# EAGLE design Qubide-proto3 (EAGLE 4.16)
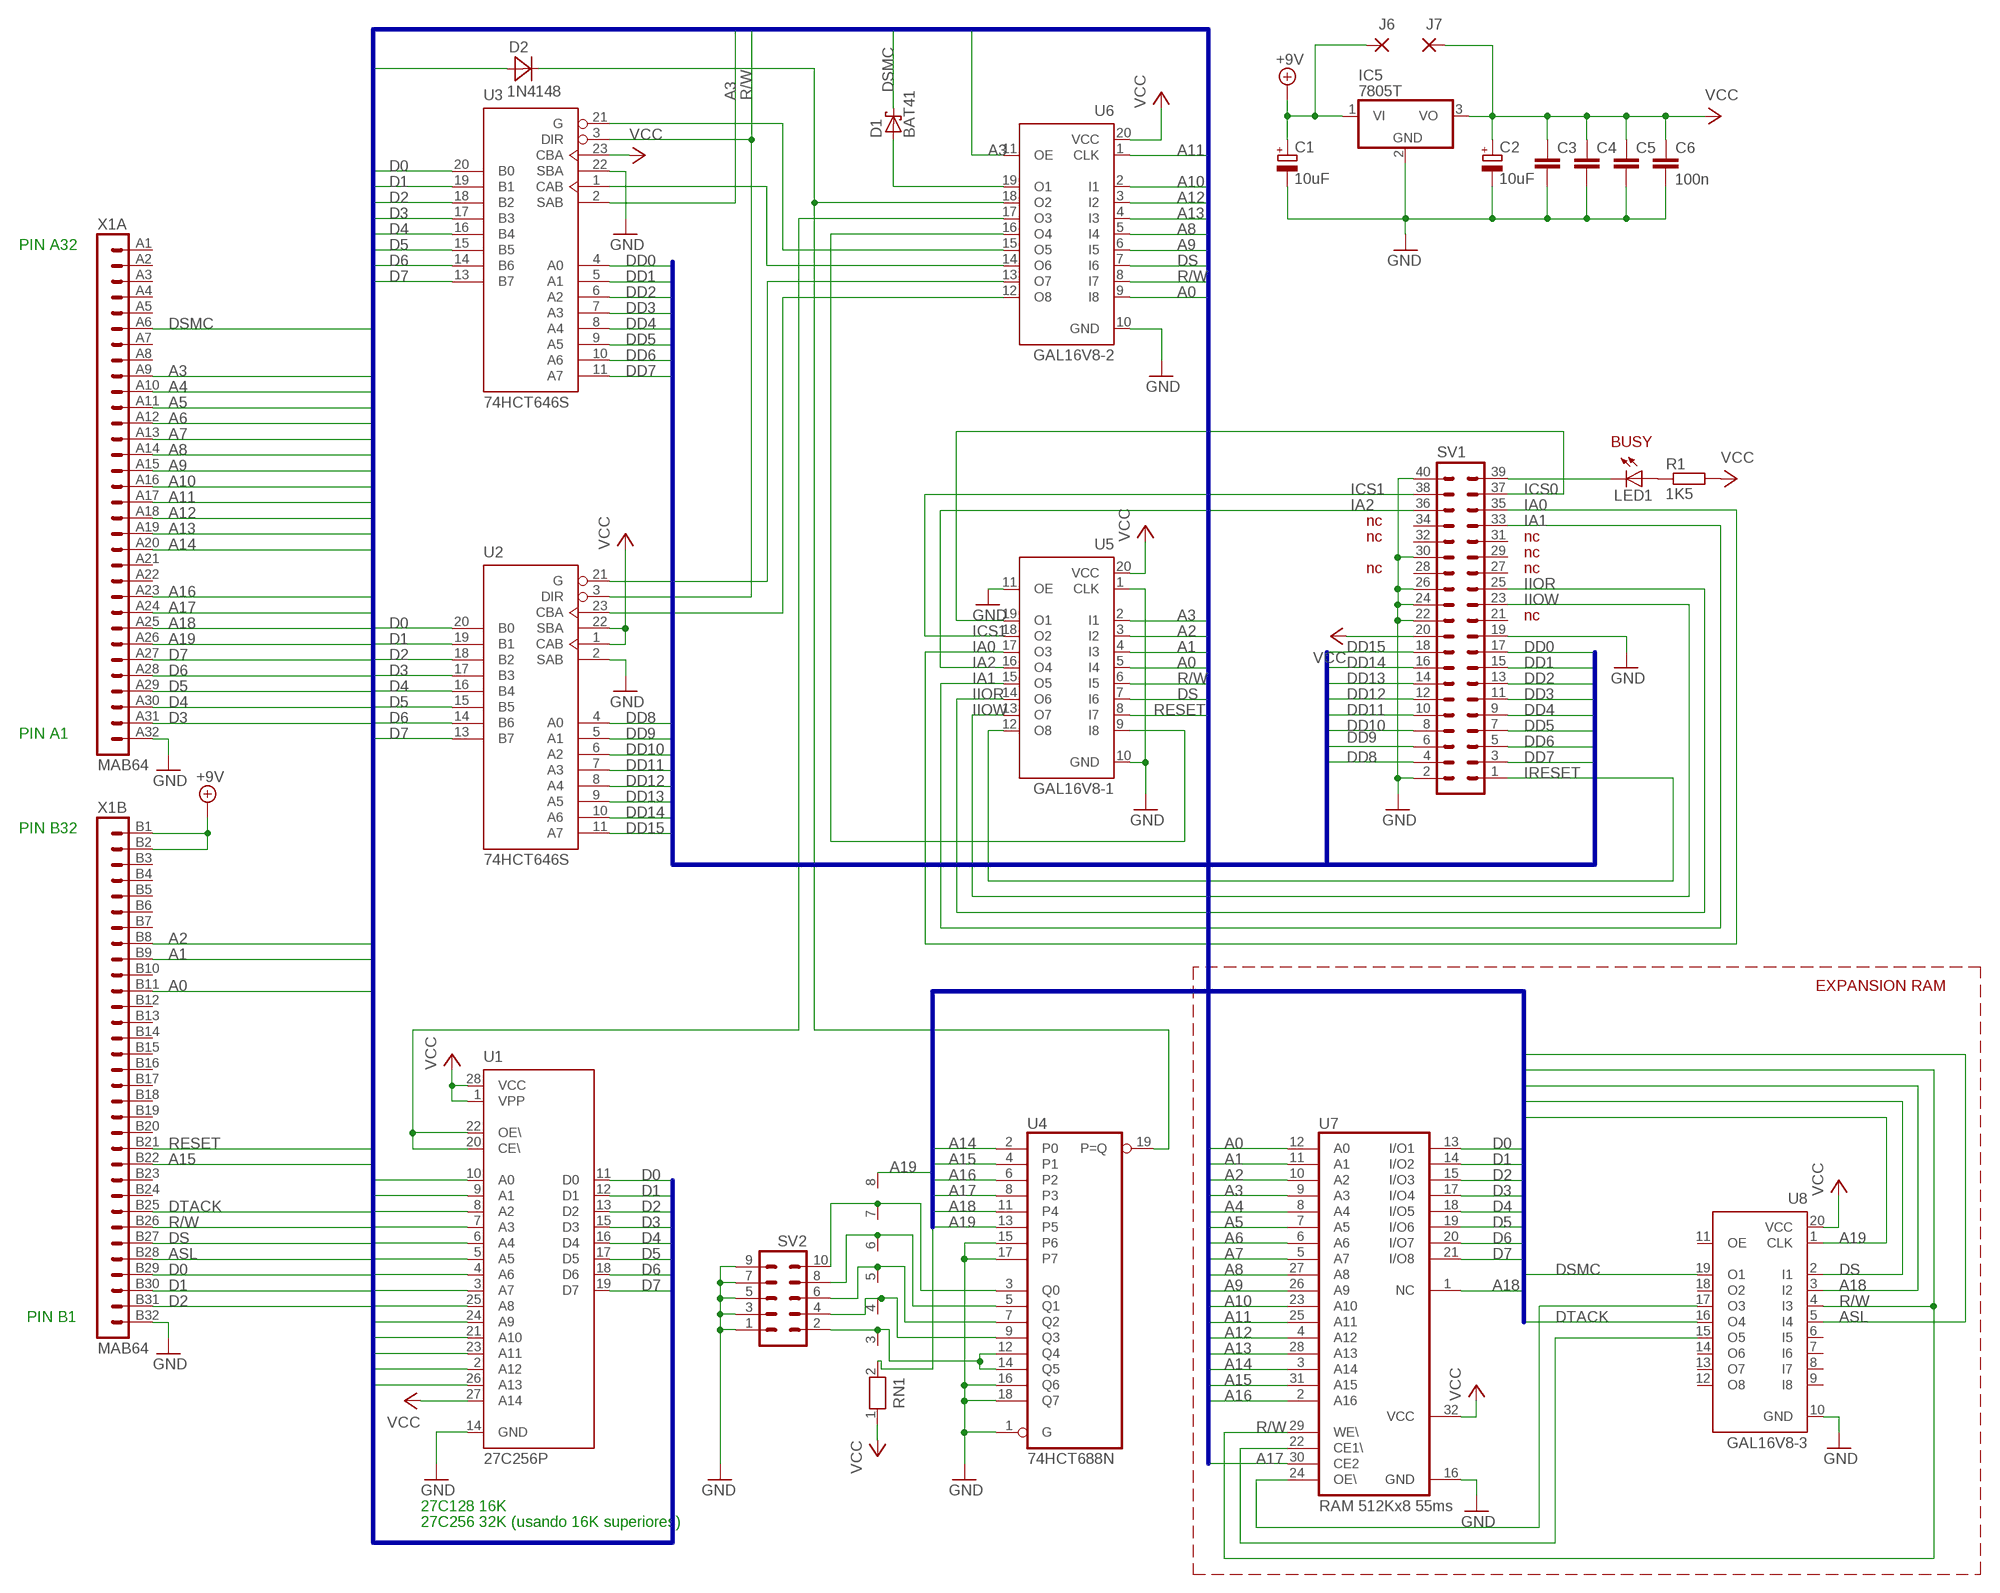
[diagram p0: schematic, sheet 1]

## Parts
C1  10uF  CPOL-EUE2.5-5  [E2,5-5]
C2  10uF  CPOL-EUE2.5-5  [E2,5-5]
C3  C-EU075-032X103  [C075-032X103]
C4  C-EU050-025X075  [C050-025X075]
C5  C-EU050-025X075  [C050-025X075]
C6  100n  C-EU050-025X075  [C050-025X075]
D1  BAT41  BAT49  [DO41-10]
D2  1N4148  DIODE-5  [D-5]
IC5  7805T  [TO220H]
J6  1,27-REDONDO1.0  [1,27/1,0-REDONDO]
J7  1,27-REDONDO1.0  [1,27/1,0-REDONDO]
LED1  LED3MM  [LED3MM]
R1  1K5  R-EU_0207/7  [0207/7]
RN1  RN07  [RN-8]
SV1  ML40L  [ML40L]
SV2  MA05-2  [MA05-2]
U1  27C256P  [DIL28-6]
U2  74HCT646S  74HC646S  [SO24W]
U3  74HCT646S  74HC646S  [SO24W]
U4  74HCT688N  [DIL20]
U5  GAL16V8-1  ATF16V8BP3  [DIL20]
U6  GAL16V8-2  ATF16V8BP3  [DIL20]
U7  RAM 512Kx8 55ms  431000  [DIL32]
U8  GAL16V8-3  ATF16V8BP3  [DIL20]
X1  MAB64  [MAB64]

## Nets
+9V: C1.+ IC5.1(VI) J6.P$1(P) X1.B1 X1.B2
A0: U1.10(A0) U5.5(I4) U6.9(I8) U7.12(A0) X1.B11
A1: U1.9(A1) U5.4(I3) U7.11(A1) X1.B9
A2: U1.8(A2) U5.3(I2) U7.10(A2) X1.B8
A3: U1.7(A3) U3.2(SAB) U5.2(I1) U6.11(OE) U7.9(A3) X1.A9
A4: U1.6(A4) U7.8(A4) X1.A10
A5: U1.5(A5) U7.7(A5) X1.A11
A6: U1.4(A6) U7.6(A6) X1.A12
A7: U1.3(A7) U7.5(A7) X1.A13
A8: U1.25(A8) U6.5(I4) U7.27(A8) X1.A14
A9: U1.24(A9) U6.6(I5) U7.26(A9) X1.A15
A10: U1.21(A10) U6.2(I1) U7.23(A10) X1.A16
A11: U1.23(A11) U6.1(CLK) U7.25(A11) X1.A17
A12: U1.2(A12) U6.3(I2) U7.4(A12) X1.A18
A13: U1.26(A13) U6.4(I3) U7.28(A13) X1.A19
A14: U4.2(P0) U7.3(A14) X1.A20
A15: U4.4(P1) U7.31(A15) X1.B22
A16: U4.6(P2) U7.2(A16) X1.A23
A17: U4.8(P3) U7.30(CE2) X1.A24
A18: RN1.2 U4.11(P4) U7.1(NC) U8.3(I2) X1.A25
A19: RN1.8 U4.13(P5) U8.1(CLK) X1.A26
ASL: U8.5(I4) X1.B28
CE-RAM: U7.22(CE1\) U8.15(O5)
D0: U1.11(D0) U2.20(B0) U3.20(B0) U7.13(I/O1) X1.B29
D1: U1.12(D1) U2.19(B1) U3.19(B1) U7.14(I/O2) X1.B30
D2: U1.13(D2) U2.18(B2) U3.18(B2) U7.15(I/O3) X1.B31
D3: U1.15(D3) U2.17(B3) U3.17(B3) U7.17(I/O4) X1.A31
D4: U1.16(D4) U2.16(B4) U3.16(B4) U7.18(I/O5) X1.A30
D5: U1.17(D5) U2.15(B5) U3.15(B5) U7.19(I/O6) X1.A29
D6: U1.18(D6) U2.14(B6) U3.14(B6) U7.20(I/O7) X1.A28
D7: U1.19(D7) U2.13(B7) U3.13(B7) U7.21(I/O8) X1.A27
DD0: SV1.17 U3.4(A0)
DD1: SV1.15 U3.5(A1)
DD2: SV1.13 U3.6(A2)
DD3: SV1.11 U3.7(A3)
DD4: SV1.9 U3.8(A4)
DD5: SV1.7 U3.9(A5)
DD6: SV1.5 U3.10(A6)
DD7: SV1.3 U3.11(A7)
DD8: SV1.4 U2.4(A0)
DD9: SV1.6 U2.5(A1)
DD10: SV1.8 U2.6(A2)
DD11: SV1.10 U2.7(A3)
DD12: SV1.12 U2.8(A4)
DD13: SV1.14 U2.9(A5)
DD14: SV1.16 U2.10(A6)
DD15: SV1.18 U2.11(A7)
DS: U5.7(I6) U6.7(I6) U8.2(I1) X1.B27
DSMC: D1.C U8.19(O1) X1.A6
DTACK: D2.A U8.16(O4) X1.B25
GND: C1.- C2.- C3.2 C4.2 C5.2 C6.2 IC5.2(GND) SV1.2 SV1.19 SV1.22 SV1.24 SV1.26 SV1.30 SV1.40 SV2.1 SV2.3 SV2.5 SV2.7 SV2.9 U1.14(GND) U2.2(SAB) U3.22(SBA) U4.1(G) U4.15(P6) U4.16(Q6) U4.17(P7) U4.18(Q7) U5.1(CLK) U5.10(GND) U5.11(OE) U6.10(GND) U7.16(GND) U8.10(GND) X1.A32 X1.B32
IA0: SV1.35 U5.17(O3)
IA1: SV1.33 U5.15(O5)
IA2: SV1.36 U5.16(O4)
ICS0: SV1.37 U5.19(O1)
ICS1: SV1.38 U5.18(O2)
IIOR: SV1.25 U5.14(O6)
IIOW: SV1.23 U5.13(O7)
IRESET: SV1.1 U5.12(O8)
N$1: D1.A U6.19(O1)
N$2: D2.C(K) U4.19(P=Q) U6.18(O2)
N$3: U1.20(CE\) U1.22(OE\) U6.17(O3)
N$4: U5.9(I8) U6.16(O4)
N$5: U3.21(G) U6.15(O5)
N$6: U3.1(CAB) U6.14(O6)
N$7: U2.21(G) U6.13(O7)
N$8: U2.23(CBA) U6.12(O8)
N$9: RN1.3 SV2.2 U4.12(Q4) U4.14(Q5)
N$10: RN1.4 SV2.4 U4.9(Q3)
N$11: RN1.5 SV2.6 U4.7(Q2)
N$12: RN1.6 SV2.8 U4.5(Q1)
N$13: RN1.7 SV2.10 U4.3(Q0)
N$14: LED1.A R1.1
N$15: LED1.K(C) SV1.39
OE-RAM: U7.24(OE\) U8.17(O3)
R/W: U2.3(DIR) U3.3(DIR) U5.6(I5) U6.8(I7) U7.29(WE\) U8.4(I3) X1.B26
RESET: U5.8(I7) X1.B21
VCC: C2.+ C3.1 C4.1 C5.1 C6.1 IC5.3(VO) J7.P$1(P) R1.2 RN1.1 SV1.20 U1.1(VPP) U1.27(A14) U1.28(VCC) U2.1(CAB) U2.22(SBA) U3.23(CBA) U5.20(VCC) U6.20(VCC) U7.32(VCC) U8.20(VCC)
Unconnected: SV1.21 SV1.27 SV1.28 SV1.29 SV1.31 SV1.32 SV1.34 U8.6(I5) U8.7(I6) U8.8(I7) U8.9(I8) U8.11(OE) U8.12(O8) U8.13(O7) U8.14(O6) U8.18(O2) X1.A1 X1.A2 X1.A3 X1.A4 X1.A5 X1.A7 X1.A8 X1.A21 X1.A22 X1.B3 X1.B4 X1.B5 X1.B6 X1.B7 X1.B10 X1.B12 X1.B13 X1.B14 X1.B15 X1.B16 X1.B17 X1.B18 X1.B19 X1.B20 X1.B23 X1.B24

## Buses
A[0..19],D[0..7],DSMC,DTACK,R/W,DS,RESET,ASL
DD[0..15]

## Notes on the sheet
- PIN A32
- BUSY
- nc
- nc | nc
- nc
- nc | nc
- nc
- PIN A1
- PIN B32
- EXPANSION RAM
- PIN B1
- 27C128 16K
- 27C256 32K (usando 16K superiores)

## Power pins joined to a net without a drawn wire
GND: U2.12(GND) U3.12(GND) U4.10(GND)
VCC: U2.24(VCC) U3.24(VCC) U4.20(VCC)

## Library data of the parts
C1 C2 = rcl:CPOL-EU: POLARIZED CAPACITOR, European symbol
C3-C6 = rcl:C-EU: CAPACITOR, European symbol
D1 = diode:BAT49: DIODE
D2 = discrete2:DIODE-5
IC5 = linear:78*: Positive VOLTAGE REGULATOR Source: http://cache.national.com/ds/LM/LM78L05.pdf http://www.fairchildsemi.com/ds/LM/LM7805.pdf
J6 J7 = wirepad2:1,27-REDONDO
LED1 = led:LED: LED
R1 = rcl:R-EU_: RESISTOR, European symbol
RN1 = discrete2:RN07
SV1 = con-harting-ml:ML40: HARTING
SV2 = con-lstb:MA05-2: PIN HEADER
U1 = microchip:27*256: CMOS EPROM 256 K (32 K x 8), low voltage
U2 U3 = 74xx-eu2:74*646
U4 = 74xx-eu:74*688: 8-bit MAGNITUDE/IDENTITY COMPARATOR, totem pole
U5 U6 U8 = atmel:ATF16V8B: High perfomance CMOS (electrically erasable) programmable logic device (PLD) ABLE-Atmel-ABEL - P18V8R, P16V8C, P16V8AS, P17V8 COPL Atmel-WinCUPL - G16V8MS, G16V8MA, G16V8AS, G16V8 LOG/IC - GAL16V8_R, GAL16V8_G7, GAL16V8_C), GAL16V8 Tango-PLD - G16V8R, G16V8C, G16V8AS, G16V8 Source: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
U7 = memory-nec:431000: MEMORY
X1 = con-vg:MAB64: CONNECTOR male, 94 pins, type B, rows AB, grid 2.54 mm

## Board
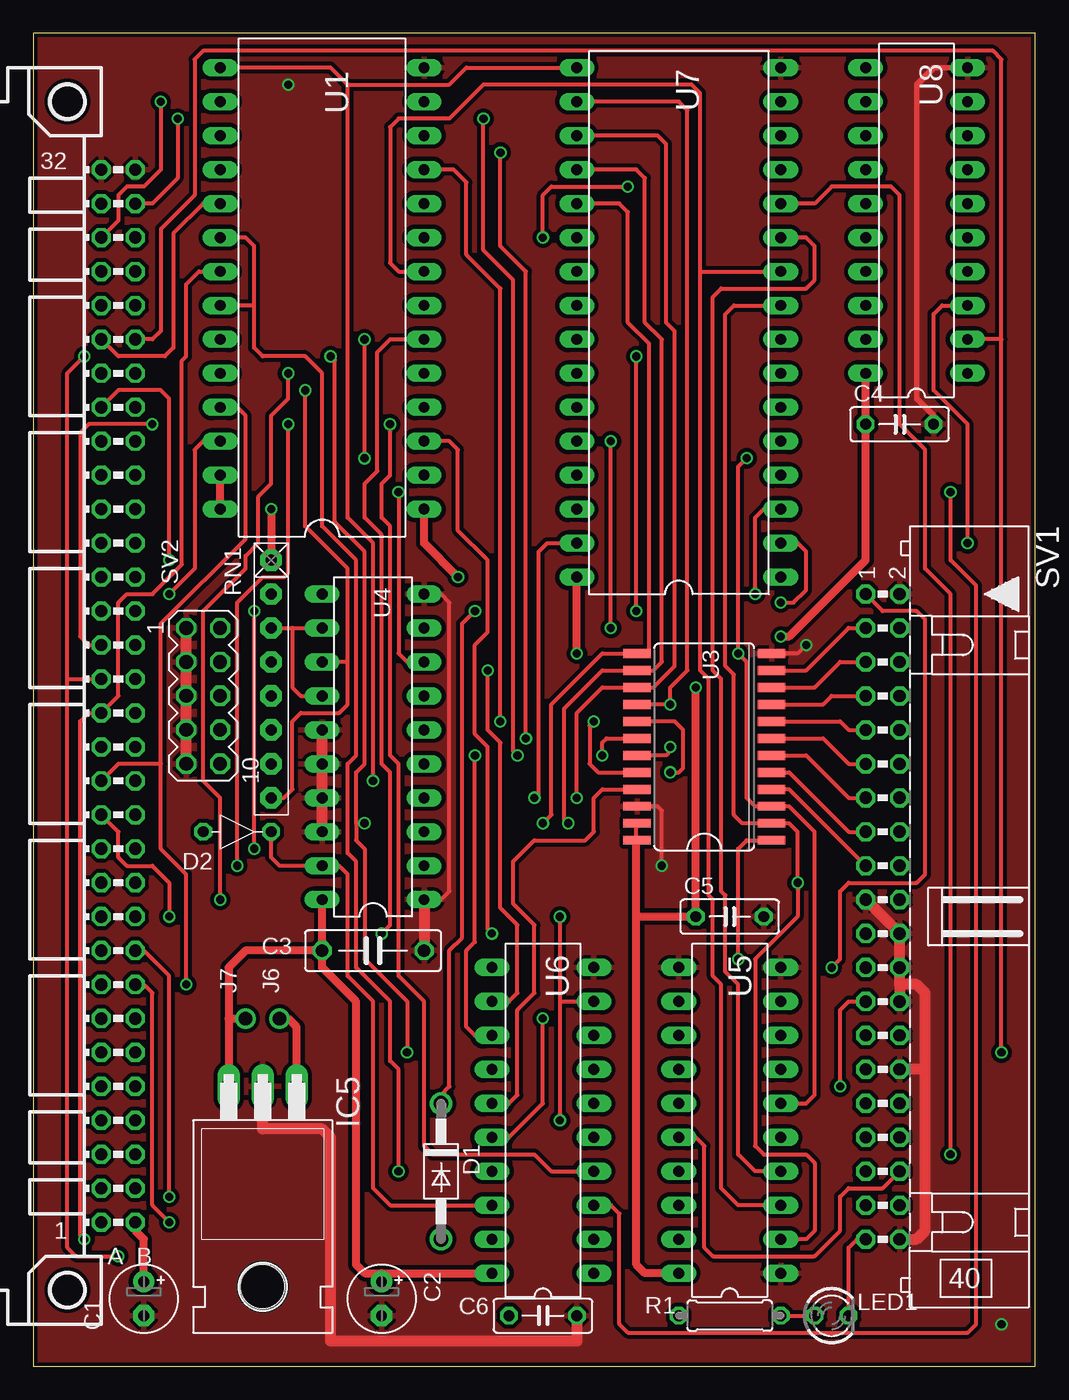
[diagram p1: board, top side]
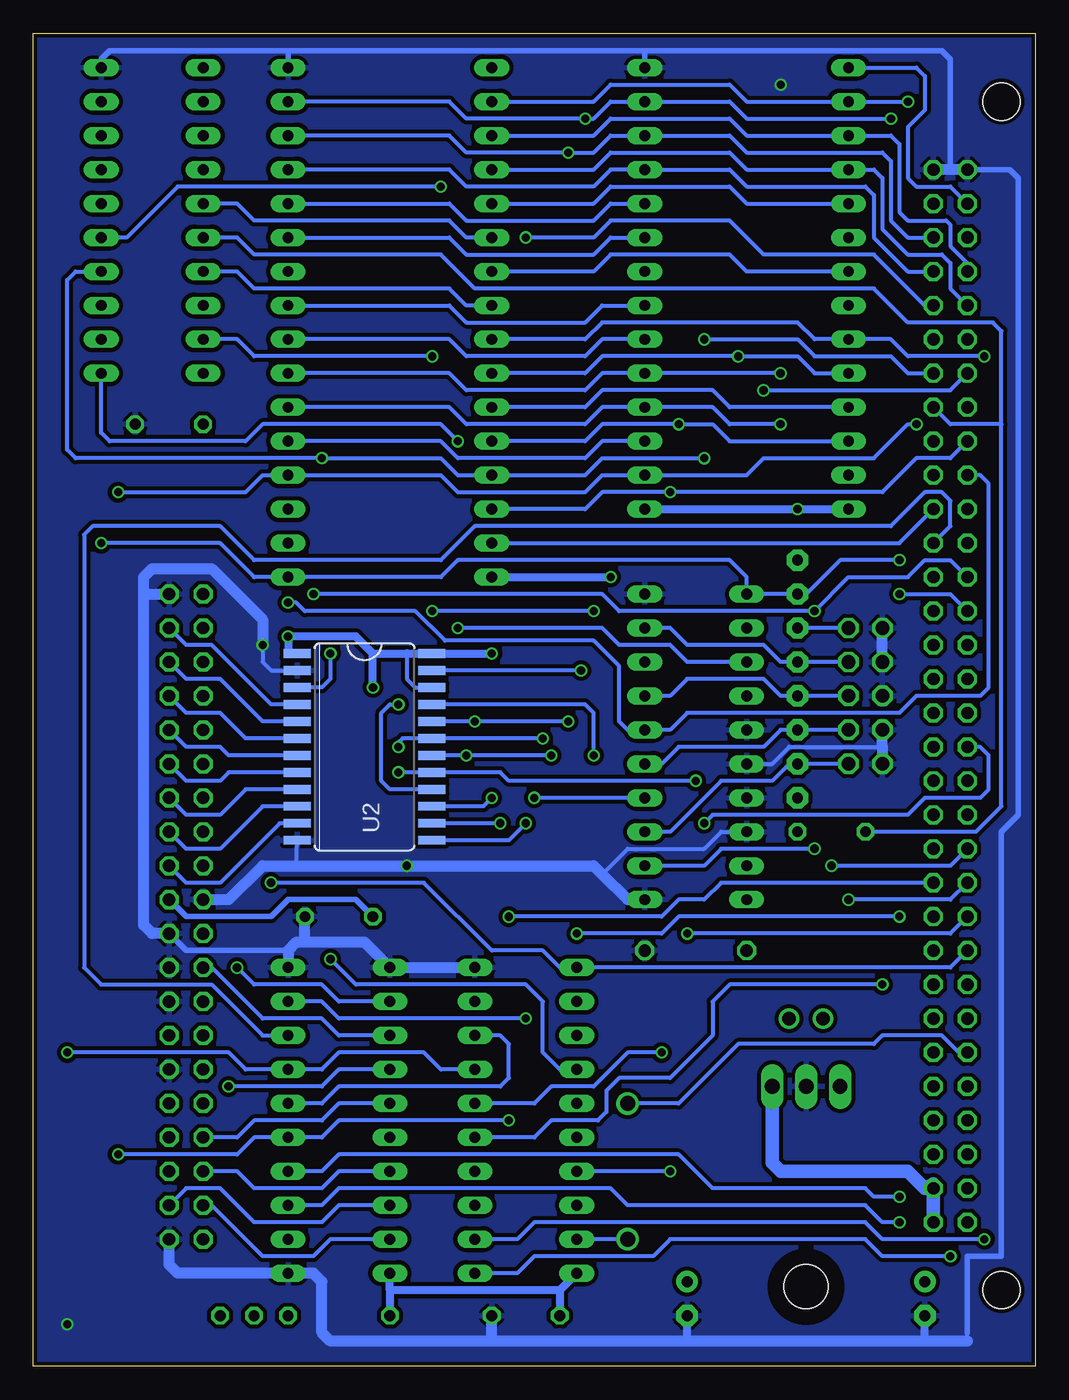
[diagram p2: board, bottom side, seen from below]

Size 74.91 x 99.68 mm. Coordinates in mm from the lower left corner, seen from the top.
Outline: 0,0 74.91,0 74.91,99.68 0,99.68 0,0
Copper layers (1*16): Top 0.035mm / dielectric 1.5mm / Bottom 0.035mm
Design rules "ITEADstudio_DRC": minimum track width 6mil, minimum drill 12mil, track to track 6mil, track to pad 6mil, pad to pad 6mil, via to via 6mil, smd to smd 0mil, copper to edge 10mil, drill to drill 10mil, minimum pad ring 10mil, minimum via ring 6mil, stop-mask expansion 2mil, vias tented up to drill 100mil, thermal gap 10mil

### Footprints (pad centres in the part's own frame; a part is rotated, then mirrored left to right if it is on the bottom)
E2,5-5 = drill 0.813 pad 1.6 round: + -1.27,0 | drill 0.813 pad 1.6 octagon: - 1.27,0
C075-032X103 = drill 0.914 octagon: 1 -3.81,0; 2 3.81,0
C050-025X075 = drill 0.813 octagon: 1 -2.54,0; 2 2.54,0
DO41-10 = drill 1.118 round: A 5.08,0; C -5.08,0
D-5 = drill 0.813 octagon: A -2.54,0; C 2.54,0
TO220H = drill 1.118 long: 1 -2.54,-10.16; 2 0,-10.16; 3 2.54,-10.16 | hole 3.302: 0,4.826
1,27/1,0-REDONDO = drill 1.016 pad 1.422 round: P$1 0,0
LED3MM = drill 0.813 octagon: A -1.27,0; K 1.27,0
0207/7 = drill 0.813 octagon: 1 -3.81,0; 2 3.81,0
RN-8 = drill 0.813 pad 1.6 octagon: 1 -8.89,0; 2 -6.35,0; 3 -3.81,0; 4 -1.27,0; 5 1.27,0; 6 3.81,0; 7 6.35,0; 8 8.89,0
ML40L = drill 0.914 octagon: 1 -24.13,-1.27; 2 -24.13,1.27; 3 -21.59,-1.27; 4 -21.59,1.27; 5 -19.05,-1.27; 6 -19.05,1.27; 7 -16.51,-1.27; 8 -16.51,1.27; 9 -13.97,-1.27; 10 -13.97,1.27; 11 -11.43,-1.27; 12 -11.43,1.27; 13 -8.89,-1.27; 14 -8.89,1.27; 15 -6.35,-1.27; 16 -6.35,1.27; 17 -3.81,-1.27; 18 -3.81,1.27; 19 -1.27,-1.27; 20 -1.27,1.27; 21 1.27,-1.27; 22 1.27,1.27; 23 3.81,-1.27; 24 3.81,1.27; 25 6.35,-1.27; 26 6.35,1.27; 27 8.89,-1.27; 28 8.89,1.27; 29 11.43,-1.27; 30 11.43,1.27; 31 13.97,-1.27; 32 13.97,1.27; 33 16.51,-1.27; 34 16.51,1.27; 35 19.05,-1.27; 36 19.05,1.27; 37 21.59,-1.27; 38 21.59,1.27; 39 24.13,-1.27; 40 24.13,1.27
MA05-2 = drill 1.016 octagon: 1 -5.08,-1.27; 2 -5.08,1.27; 3 -2.54,-1.27; 4 -2.54,1.27; 5 0,-1.27; 6 0,1.27; 7 2.54,-1.27; 8 2.54,1.27; 9 5.08,-1.27; 10 5.08,1.27
DIL28-6 = drill 0.813 long: 1 -16.51,-7.62; 2 -13.97,-7.62; 3 -11.43,-7.62; 4 -8.89,-7.62; 5 -6.35,-7.62; 6 -3.81,-7.62; 7 -1.27,-7.62; 8 1.27,-7.62; 9 3.81,-7.62; 10 6.35,-7.62; 11 8.89,-7.62; 12 11.43,-7.62; 13 13.97,-7.62; 14 16.51,-7.62; 15 16.51,7.62; 16 13.97,7.62; 17 11.43,7.62; 18 8.89,7.62; 19 6.35,7.62; 20 3.81,7.62; 21 1.27,7.62; 22 -1.27,7.62; 23 -3.81,7.62; 24 -6.35,7.62; 25 -8.89,7.62; 26 -11.43,7.62; 27 -13.97,7.62; 28 -16.51,7.62
SO24W = smd 0.66 x 2.032: 1 -6.985,-5.029; 2 -5.715,-5.029; 3 -4.445,-5.029; 4 -3.175,-5.029; 5 -1.905,-5.029; 6 -0.635,-5.029; 7 0.635,-5.029; 8 1.905,-5.029; 9 3.175,-5.029; 10 4.445,-5.029; 11 5.715,-5.029; 12 6.985,-5.029; 13 6.985,5.029; 14 5.715,5.029; 15 4.445,5.029; 16 3.175,5.029; 17 1.905,5.029; 18 0.635,5.029; 19 -0.635,5.029; 20 -1.905,5.029; 21 -3.175,5.029; 22 -4.445,5.029; 23 -5.715,5.029; 24 -6.985,5.029
DIL20 = drill 0.813 long: 1 -11.43,-3.81; 2 -8.89,-3.81; 3 -6.35,-3.81; 4 -3.81,-3.81; 5 -1.27,-3.81; 6 1.27,-3.81; 7 3.81,-3.81; 8 6.35,-3.81; 9 8.89,-3.81; 10 11.43,-3.81; 11 11.43,3.81; 12 8.89,3.81; 13 6.35,3.81; 14 3.81,3.81; 15 1.27,3.81; 16 -1.27,3.81; 17 -3.81,3.81; 18 -6.35,3.81; 19 -8.89,3.81; 20 -11.43,3.81
DIL32 = drill 0.813 long: 1 -19.05,-7.62; 2 -16.51,-7.62; 3 -13.97,-7.62; 4 -11.43,-7.62; 5 -8.89,-7.62; 6 -6.35,-7.62; 7 -3.81,-7.62; 8 -1.27,-7.62; 9 1.27,-7.62; 10 3.81,-7.62; 11 6.35,-7.62; 12 8.89,-7.62; 13 11.43,-7.62; 14 13.97,-7.62; 15 16.51,-7.62; 16 19.05,-7.62; 17 19.05,7.62; 18 16.51,7.62; 19 13.97,7.62; 20 11.43,7.62; 21 8.89,7.62; 22 6.35,7.62; 23 3.81,7.62; 24 1.27,7.62; 25 -1.27,7.62; 26 -3.81,7.62; 27 -6.35,7.62; 28 -8.89,7.62; 29 -11.43,7.62; 30 -13.97,7.62; 31 -16.51,7.62; 32 -19.05,7.62
MAB64 = drill 0.914 octagon: A1 -2.54,39.37; A2 -2.54,36.83; A3 -2.54,34.29; A4 -2.54,31.75; A5 -2.54,29.21; A6 -2.54,26.67; A7 -2.54,24.13; A8 -2.54,21.59; A9 -2.54,19.05; A10 -2.54,16.51; A11 -2.54,13.97; A12 -2.54,11.43; A13 -2.54,8.89; A14 -2.54,6.35; A15 -2.54,3.81; A16 -2.54,1.27; A17 -2.54,-1.27; A18 -2.54,-3.81; A19 -2.54,-6.35; A20 -2.54,-8.89; A21 -2.54,-11.43; A22 -2.54,-13.97; A23 -2.54,-16.51; A24 -2.54,-19.05; A25 -2.54,-21.59; A26 -2.54,-24.13; A27 -2.54,-26.67; A28 -2.54,-29.21; A29 -2.54,-31.75; A30 -2.54,-34.29; A31 -2.54,-36.83; A32 -2.54,-39.37; B1 -5.08,39.37; B2 -5.08,36.83; B3 -5.08,34.29; B4 -5.08,31.75; B5 -5.08,29.21; B6 -5.08,26.67; B7 -5.08,24.13; B8 -5.08,21.59; B9 -5.08,19.05; B10 -5.08,16.51; B11 -5.08,13.97; B12 -5.08,11.43; B13 -5.08,8.89; B14 -5.08,6.35; B15 -5.08,3.81; B16 -5.08,1.27; B17 -5.08,-1.27; B18 -5.08,-3.81; B19 -5.08,-6.35; B20 -5.08,-8.89; B21 -5.08,-11.43; B22 -5.08,-13.97; B23 -5.08,-16.51; B24 -5.08,-19.05; B25 -5.08,-21.59; B26 -5.08,-24.13; B27 -5.08,-26.67; B28 -5.08,-29.21; B29 -5.08,-31.75; B30 -5.08,-34.29; B31 -5.08,-36.83; B32 -5.08,-39.37 | hole 2.794: 0,44.45; 0,-44.45

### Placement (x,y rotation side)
C1  8.25,5.04 270 top
C2  26.03,5.04 270 top
C3  25.39,31.08 0 top
C4  64.77,70.45 0 top
C5  52.06,33.62 0 top
C6  38.09,3.77 0 top
D1  30.48,14.57 270 top
D2  15.23,39.97 0 top
IC5  17.14,10.76 180 top
J6  18.41,26 270 top
J7  15.87,26 90 top
LED1  59.68,3.77 0 top
R1  52.06,3.77 180 top
RN1  17.78,51.4 270 top
SV1  63.49,33.62 270 top
SV2  12.69,50.13 270 top
U1  21.59,80.61 90 top
U2  50.16,46.32 270 bottom
U3  50.16,46.32 90 top
U4  25.39,46.32 90 top
U5  52.06,18.38 90 top
U6  38.09,18.38 90 top
U7  48.25,78.07 90 top
U8  66.04,85.69 90 top
X1  2.54,50.13 180 top

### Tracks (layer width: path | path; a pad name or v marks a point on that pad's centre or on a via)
+9V
  Top 0.61: J6.P$1 19.05,26 19.68,25.36 IC5.1 | C1.+ 8.25,9.49 7.62,10.12 X1.B1
  Bottom 0.813: X1.B2 7.62,13.61
  Bottom 1.016: X1.B1 X1.B2 | 7.62,13.61 8.25,13.3 9.52,14.57 19.05,14.57 19.68,15.2 IC5.1
A0  (via drill 0.61)
  Top 0.305: 39.36,27.27 v39.36,18.38 | v39.36,33.62 39.36,27.27 | 39.36,27.27 U6.9 | v68.58,15.84 68.58,57.75 66.67,59.65 66.67,68.54 64.77,70.45 64.77,87.59 64.13,88.23 59.68,88.23 58.41,86.96 U7.12
  Bottom 0.305: U1.10 31.75,86.96 33.02,85.69 42.54,85.69 43.81,86.96 U7.12 | v39.36,18.38 52.06,18.38 53.34,17.11 U5.5 58.41,17.11 59.68,15.84 v68.58,15.84 | v39.36,33.62 27.94,33.62 26.67,34.89 24.76,34.89 23.49,36.16 X1.B11
A1  (via drill 0.61)
  Top 0.305: v10.15,12.66 10.15,29.17 8.25,31.08 X1.B9 | U5.4 53.97,14.57 52.7,15.84 52.7,28.54 51.75,29.49 51.75,35.2 51.43,35.52 51.43,51.4 50.79,52.03 50.79,79.97 51.43,80.61 57.78,80.61 58.41,81.24 58.41,83.78 57.78,84.42 U7.11
  Bottom 0.305: U1.9 31.75,84.42 33.02,83.15 42.54,83.15 43.81,84.42 U7.11 | v10.15,12.66 12.06,12.66 12.69,13.3 24.12,13.3 26.67,15.84 52.06,15.84 53.34,14.57 U5.4
A2  (via drill 0.61)
  Top 0.305: 49.84,81.88 49.84,95.21 49.21,95.85 33.65,95.85 31.11,93.31 27.3,93.31 26.67,92.67 26.67,82.51 27.3,81.88 U1.8 | 49.84,81.88 U7.10 | v10.15,10.76 8.88,12.03 8.88,27.9 8.25,28.54 X1.B8 | 49.84,81.88 49.84,52.03 50.48,51.4 50.48,35.2 50.79,34.89 50.79,29.17 51.43,28.54 51.43,13.3 52.7,12.03 U5.3
  Bottom 0.305: v10.15,10.76 11.42,10.76 12.69,12.03 30.48,12.03 31.75,13.3 52.06,13.3 53.34,12.03 U5.3
A3  (via drill 0.61)
  Top 0.305: U3.2 56.51,40.6 57.14,39.97 v57.14,36.16 57.14,33.62 53.97,30.44 53.97,16.47 54.6,15.84 57.78,15.84 58.41,15.2 58.41,10.12 57.78,9.49 U5.2 | U7.9 52.38,79.34 51.75,78.7 51.75,52.35 52.38,51.71 52.38,41.24 53.02,40.6 U3.2 | U3.2 55.24,40.6
  Bottom 0.305: X1.A9 6.34,29.81 U6.11 35.55,29.81 36.82,31.08 40.63,31.08 45.71,36.16 v57.14,36.16 | U1.7 32.38,79.34 33.65,78.07 42.54,78.07 43.81,79.34 U7.9
A4  (via drill 0.6)
  Top 0.305: U1.6 26.67,76.8 25.71,75.84 25.71,66.95 24.76,66 24.76,63.46 26.03,62.19 26.03,45.05 26.67,44.41 26.67,32.98 v26.03,32.35
  Bottom 0.305: U1.6 32.38,76.8 33.65,75.53 42.54,75.53 43.81,76.8 U7.8 | X1.A10 6.34,32.35 v26.03,32.35
A5  (via drill 0.61)
  Top 0.305: v13.96,34.89 13.96,42.51 12.69,43.78 12.69,56.48 15.87,59.65 15.87,60.6 16.82,61.56 16.82,65.05 17.78,66 17.78,71.08 19.05,72.35 v19.05,74.26
  Bottom 0.305: U7.7 43.81,74.26 42.54,72.99 33.65,72.99 32.38,74.26 U1.5 v19.05,74.26 | X1.A11 6.34,34.89 v13.96,34.89
A6  (via drill 0.61)
  Top 0.305: v15.23,37.43 15.23,57.11 17.14,59.02 18.73,59.02 19.05,59.34 v19.05,70.45
  Bottom 0.305: U7.6 43.81,71.72 42.54,70.45 33.65,70.45 32.38,71.72 U1.4 24.12,71.72 22.86,70.45 v19.05,70.45 | v15.23,37.43 6.34,37.43 X1.A12
A7  (via drill 0.6)
  Top 0.305: U1.3 31.11,69.18 31.75,68.54 31.75,62.51 33.97,60.29 33.97,54.89 33.02,53.94 33.02,47.27 33.97,46.32 33.97,32.67 v34.28,32.35 | X1.A13 6.34,39.97 6.34,38.06 6.98,37.43 8.88,37.43 10.15,36.16 v10.15,33.62
  Bottom 0.305: U1.3 32.38,69.18 33.65,67.91 43.17,67.91 44.45,69.18 U7.5 | v10.15,33.62 26.67,33.62 27.94,32.35 v34.28,32.35
A8  (via drill 0.6)
  Top 0.305: v11.42,28.54 11.42,36.79 9.52,38.7 9.52,45.05 | 9.52,45.05 6.34,45.05 X1.A14 | U1.25 15.23,71.72 15.87,71.08 15.87,61.88 9.52,55.52 9.52,45.05
  Bottom 0.305: U1.25 22.86,71.72 24.12,72.99 32.38,72.99 33.65,71.72 U7.27 | U6.5 37.46,17.11 36.19,18.38 32.7,18.38 32.06,19.01 32.06,20.6 31.11,21.55 27.3,21.55 24.12,24.73 24.12,27.27 22.86,28.54 v11.42,28.54
A9  (via drill 0.61)
  Top 0.305: v27.94,23.46 27.94,27.27 24.76,30.44 24.76,38.7 24.12,39.33 24.12,40.6 | v22.22,75.53 22.54,75.21 22.54,63.14 24.76,60.92 24.76,45.05 24.12,44.41 24.12,40.6 | v24.76,40.6 24.12,40.6
  Bottom 0.305: U1.24 16.51,74.26 17.78,75.53 v22.22,75.53 32.38,75.53 33.65,74.26 U7.26 | U6.6 37.46,19.65 36.19,20.92 33.02,20.92 30.48,23.46 v27.94,23.46 | v24.76,40.6 24.12,41.24 9.52,41.24 8.25,42.51 4.12,42.51 3.49,43.14 3.49,45.68 4.12,46.32 X1.A15
A10  (via drill 0.61)
  Top 0.305: v3.81,9.49 3.49,9.8 3.49,48.22 4.12,48.86 X1.A16 6.34,50.13 6.34,57.11 6.98,57.75 8.88,57.75 11.11,59.97 11.11,75.21 11.42,75.53 11.42,80.92 12.38,81.88 U1.21
  Bottom 0.305: U1.21 21.59,81.88 22.86,83.15 31.75,83.15 33.02,81.88 U7.23 | v3.81,9.49 11.42,9.49 12.69,10.76 37.46,10.76 38.73,9.49 U6.2
A11  (via drill 0.61)
  Top 0.305: v6.34,8.22 3.17,8.22 2.54,8.85 2.54,51.4 | 2.54,51.4 X1.A17 | 2.54,51.4 2.54,74.26 v3.81,75.53
  Bottom 0.305: U7.25 33.65,76.8 32.38,78.07 17.78,78.07 16.51,76.8 U1.23 10.79,76.8 9.52,75.53 v3.81,75.53 | v6.34,8.22 11.42,8.22 12.69,9.49 27.3,9.49 28.57,8.22 37.46,8.22 38.73,6.95 U6.1
A12  (via drill 0.61)
  Top 0.305: v68.58,65.37 68.58,60.29 70.48,58.38 70.48,3.14 69.84,2.5 44.45,2.5 43.81,3.14 43.81,11.39 43.17,12.03 U6.3 | v8.88,70.45 4.12,70.45 3.49,69.81 3.49,54.57 4.12,53.94 X1.A18
  Bottom 0.305: v68.58,65.37 59.05,65.37 57.78,66.64 U7.4 44.45,66.64 43.17,65.37 33.65,65.37 32.38,66.64 U1.2 21.59,66.64 20.32,67.91 12.06,67.91 9.52,70.45 v8.88,70.45
A13  (via drill 0.61)
  Top 0.305: v26.67,70.45 26.67,66.64 26.03,66 26.03,63.46 26.67,62.83 26.67,45.68 27.3,45.05 27.3,29.17 29.21,27.27 29.21,16.47 29.84,15.84 37.46,15.84 38.73,14.57 U6.4 | v10.15,57.75 12.06,59.65 12.06,68.54 12.69,69.18 U1.26
  Bottom 0.305: U1.26 22.86,69.18 24.12,70.45 v26.67,70.45 32.38,70.45 33.65,69.18 U7.28 | v10.15,57.75 6.34,57.75 X1.A19
A14  (via drill 0.61)
  Top 0.305: v53.97,57.75 53.97,63.46 54.6,64.1 U7.3 | v16.51,38.7 v16.51,56.48
  Bottom 0.305: v16.51,38.7 23.49,38.7 24.76,37.43 U4.2 | v53.97,57.75 32.38,57.75 31.11,56.48 v16.51,56.48 13.96,59.02 9.52,59.02 8.25,60.29 6.34,60.29 X1.A20
A15  (via drill 0.61)
  Top 0.305: v37.46,42.51 37.78,42.82 37.78,60.92 38.41,61.56 U7.31
  Bottom 0.305: U4.4 v37.46,42.51 | X1.B22 10.15,61.56 U7.31
A16  (via drill 0.61)
  Top 0.305: v55.88,57.11 56.83,57.11 57.78,58.06 57.78,60.92 57.14,61.56 U7.2
  Bottom 0.305: v55.88,57.11 55.24,57.11 54.6,56.48 46.35,56.48 44.13,54.25 33.02,54.25 31.11,52.35 31.11,48.22 30.48,47.59 U4.6 27.3,47.59 26.03,48.86 10.15,48.86 8.88,50.13 4.12,50.13 3.49,50.76 3.49,66 4.12,66.64 X1.A23
A17  (via drill 0.61)
  Top 0.305: U4.8 27.94,52.67 27.3,53.3 v27.3,65.37
  Bottom 0.305: U7.30 33.65,64.1 32.38,65.37 v27.3,65.37 11.42,65.37 8.88,67.91 6.34,67.91 X1.A24
A18  (via drill 0.61)
  Top 0.305: v69.84,61.56 69.84,70.45 67.31,72.99 67.31,78.7 67.94,79.34 U8.3 | X1.A25 6.34,72.99 9.52,72.99 10.15,72.35 v10.15,60.29
  Bottom 0.305: v69.84,61.56 60.95,61.56 58.41,59.02 U7.1 44.45,59.02 43.17,60.29 22.86,60.29 21.59,59.02 U4.11 RN1.2 17.14,57.75 14.6,60.29 v10.15,60.29
A19  (via drill 0.61)
  Top 0.305: 23.49,52.67 23.49,49.49 22.86,48.86 20,48.86 19.36,48.22 19.36,43.14 18.73,42.51 RN1.8 | 23.49,52.67 U4.13 | v43.17,55.21 v43.17,69.18 | v20.32,72.99 20.32,62.83 23.49,59.65 23.49,52.67
  Bottom 0.305: v43.17,69.18 44.45,70.45 57.78,70.45 59.05,69.18 69.21,69.18 69.84,69.81 U8.1 | v43.17,55.21 32.38,55.21 31.11,53.94 27.3,53.94 26.03,52.67 U4.13 | X1.A26 6.34,72.99 v20.32,72.99
ASL  (via drill 0.61)
  Top 0.305: v44.45,88.23 38.73,88.23 38.09,87.59 v38.09,84.42
  Bottom 0.305: v44.45,88.23 64.13,88.23 67.94,84.42 U8.5 | v38.09,84.42 33.02,84.42 31.75,85.69 22.86,85.69 20.32,83.15 12.06,83.15 8.25,79.34 X1.B28
CE-RAM
  Bottom 0.305: U7.22 42.54,84.42 43.81,85.69 58.41,85.69 59.68,86.96 U8.15
D0  (via drill 0.6)
  Top 0.305: v41.9,48.22 41.59,47.91 41.59,45.05 42.22,44.41 U3.20 | U1.11 31.43,89.5 32.38,88.54 32.38,83.15 34.92,80.61 v34.92,48.22
  Bottom 0.305: U7.13 43.81,89.5 42.54,88.23 33.02,88.23 31.75,89.5 U1.11 22.86,89.5 21.59,88.23 12.69,88.23 12.06,87.59 12.06,84.42 9.52,81.88 X1.B29 | U2.20 v41.9,48.22 v34.92,48.22
D1  (via drill 0.61)
  Top 0.305: v47.62,46.32 47.62,46 47.3,45.68 U3.19 | v36.82,46.95 36.82,81.88 34.92,83.78 v34.92,90.77
  Bottom 0.305: v47.62,46.32 47.62,46.63 47.3,46.95 U2.19 v36.82,46.95 | U7.14 43.81,92.04 42.54,90.77 v34.92,90.77 33.02,90.77 31.75,92.04 U1.12 22.86,92.04 21.59,90.77 11.42,90.77 10.79,90.13 10.79,85.69 9.52,84.42 X1.B30
D2  (via drill 0.61)
  Top 0.305: v42.54,45.68 42.54,46.63 42.86,46.95 U3.18 | v36.19,45.68 35.87,46 35.87,81.24 33.65,83.46 v33.65,93.31 | v10.79,93.31 10.79,88.86 8.88,86.96 X1.B31
  Bottom 0.305: U2.18 v42.54,45.68 v36.19,45.68 | U7.15 43.81,94.58 42.54,93.31 v33.65,93.31 33.02,93.31 31.75,94.58 U1.13 22.86,94.58 21.59,93.31 v10.79,93.31
D3  (via drill 0.61)
  Top 0.305: v47.62,44.41 48.25,44.41 48.57,44.73 48.57,47.59 47.94,48.22 U3.17 | v25.39,43.78 25.39,61.56 23.49,63.46 23.49,95.85 | 23.49,95.85 22.22,97.12 U1.15 | 23.49,95.85 31.11,95.85 32.38,97.12 U7.17
  Bottom 0.305: v47.62,44.41 U2.17 40,44.41 39.36,43.78 v25.39,43.78 | X1.A31 6.34,88.23 8.88,88.23 9.52,88.86 9.52,92.67 8.25,93.94 8.25,96.48 8.88,97.12 U1.15
D4  (via drill 0.61)
  Top 0.305: U3.16 v47.62,49.49 47.62,50.76 48.89,52.03 48.89,93.94 48.25,94.58 U7.18 | v9.52,94.58 9.52,89.5 8.25,88.23 6.98,88.23 6.34,87.59 6.34,85.69 X1.A30
  Bottom 0.305: v47.62,49.49 48.25,49.49 48.89,48.86 48.89,43.78 48.25,43.14 U2.16 | U7.18 33.02,94.58 31.75,95.85 22.86,95.85 21.59,94.58 U1.16 v9.52,94.58
D5  (via drill 0.6)
  Top 0.305: U3.15 46.03,50.76 | U7.19 46.67,92.04 47.3,91.4 47.3,78.07 47.94,77.43 47.94,52.35 46.35,50.76 U3.15 | v40.63,42.51 40.63,48.86 42.54,50.76 U3.15
  Bottom 0.305: U7.19 33.02,92.04 31.75,93.31 22.86,93.31 21.59,92.04 U1.17 10.79,92.04 10.15,91.4 10.15,86.32 9.52,85.69 6.66,85.69 6.34,85.37 6.34,83.78 5.08,82.51 X1.A29 | v40.63,42.51 41.27,41.87 U2.15
D6  (via drill 0.61)
  Top 0.305: v40,40.6 39.68,40.92 39.68,49.17 42.54,52.03 U3.14 46.35,52.03 46.98,52.67 46.98,76.8 45.71,78.07 45.71,88.86 45.08,89.5 U7.20
  Bottom 0.305: v40,40.6 U2.14 | X1.A28 6.34,80.61 6.34,82.51 6.98,83.15 9.52,83.15 11.42,85.05 11.42,88.86 12.06,89.5 U1.18 21.59,89.5 22.86,90.77 31.75,90.77 33.02,89.5 U7.20
D7  (via drill 0.61)
  Top 0.305: v38.09,40.6 38.73,41.24 38.73,49.49 42.54,53.3 U3.13 46.03,53.3 46.03,76.48 44.45,78.07 44.45,86.32 43.81,86.96 U7.21 | X1.A27 6.34,75.53 9.84,75.53 10.47,76.16 10.47,84.73 12.69,86.96 U1.19
  Bottom 0.305: v38.09,40.6 39.36,39.33 U2.13 | U7.21 33.02,86.96 31.75,88.23 22.86,88.23 21.59,86.96 U1.19
DD0
  Top 0.305: U3.4 56.51,43.14 SV1.17
DD1
  Top 0.305: U3.5 56.51,44.41 60.95,39.97 SV1.15
DD2
  Top 0.305: U3.6 57.78,45.68 60.95,42.51 SV1.13
DD3
  Top 0.305: U3.7 59.05,46.95 60.95,45.05 SV1.11
DD4
  Top 0.305: U3.8 60.32,48.22 60.95,47.59 SV1.9
DD5
  Top 0.305: SV1.7 59.68,50.13 59.05,49.49 U3.9
DD6
  Top 0.305: U3.10 58.41,50.76 60.32,52.67 SV1.5
DD7
  Top 0.305: U3.11 57.78,52.03 60.95,55.21 SV1.3
DD8
  Bottom 0.305: U2.4 57.14,49.49 61.59,53.94 63.49,53.94 SV1.4
DD9
  Bottom 0.305: U2.5 57.78,48.22 60.95,51.4 63.49,51.4 SV1.6
DD10
  Bottom 0.305: U2.6 59.05,46.95 60.95,48.86 63.49,48.86 SV1.8
DD11
  Bottom 0.305: U2.7 60.32,45.68 60.95,46.32 63.49,46.32 SV1.10
DD12
  Bottom 0.305: SV1.12 63.49,43.78 60.95,43.78 60.32,44.41 U2.8
DD13
  Bottom 0.305: U2.9 59.05,43.14 60.95,41.24 63.49,41.24 SV1.14
DD14
  Bottom 0.305: U2.10 57.78,41.87 60.95,38.7 63.49,38.7 SV1.16
DD15
  Bottom 0.305: SV1.18 63.49,36.16 60.95,36.16 56.51,40.6 U2.11
DS  (via drill 0.61)
  Top 0.305: v72.39,23.46 72.39,76.8 | 72.39,76.8 U8.2 | X1.B27 8.88,76.8 9.52,77.43 9.52,85.05 12.06,87.59 12.06,97.75 12.69,98.39 71.75,98.39 72.39,97.75 72.39,76.8
  Bottom 0.305: U6.7 44.45,22.19 45.71,23.46 52.06,23.46 53.34,22.19 U5.7 59.05,22.19 60.32,23.46 v72.39,23.46
DSMC  (via drill 0.61)
  Top 0.305: v45.08,56.48 v45.08,75.53 | v33.02,56.48 32.06,55.52 32.06,32.03 31.11,31.08 31.11,20.92 30.48,20.28 D1.C
  Bottom 0.305: v45.08,75.53 58.41,75.53 59.68,76.8 U8.19 | v33.02,56.48 v45.08,56.48 | X1.A6 5.71,23.46 6.98,24.73 11.42,24.73 12.06,24.09 22.22,24.09 26.67,19.65 D1.C
DTACK
  Bottom 0.305: 2.54,70.45 2.54,41.87 4.44,39.97 D2.A | 2.54,70.45 6.34,70.45 X1.B25 | U8.16 59.68,84.42 58.41,83.15 44.45,83.15 41.9,80.61 12.06,80.61 9.52,78.07 3.17,78.07 2.54,77.43 2.54,70.45
GND  (via drill 0.6, 0.61)
  Top 0.305: v46.98,37.43 46.98,41.56 46.67,41.87 U3.22 | U4.10 30.48,57.75 31.11,57.11 31.11,35.52 30.48,34.89 U4.1 | v57.78,53.94 57.14,53.3 U3.12
  Top 0.406: C4.2 67.31,71.08 66.04,72.35 66.04,95.85 67.31,97.12 U8.10
  Top 0.813: SV2.9 SV2.7 SV2.5 SV2.3 SV2.1 | U4.18 U4.17 U4.16 U4.15 | U4.1 C3.2 | SV1.40 66.04,9.49 66.67,10.12 66.67,22.19 | 66.67,22.19 SV1.30 | 64.77,28.54 SV1.26 | 64.77,28.54 66.04,28.54 66.67,27.9 66.67,22.19 | 64.77,28.54 SV1.24 SV1.22 SV1.19 | IC5.2 17.14,17.74 21.59,17.74 22.22,17.11 22.22,1.87 40.63,1.87 C6.2
  Bottom 0.305: 55.24,37.43 U2.12 | 32.38,36.79 30.48,38.7 24.76,38.7 23.49,39.97 U4.18 | 11.42,46.32 18.41,46.32 19.68,45.05 U4.16 | v57.78,53.94 57.78,52.67 57.14,52.03 U2.2 | 5.08,1.87 5.08,2.5
  Bottom 0.406: 29.21,98.39 55.88,98.39 | 29.21,98.39 U1.14 | 55.88,98.39 U7.16 | 55.88,98.39 69.21,98.39 69.84,97.75 U8.10 | 55.88,31.08 63.49,31.08 SV1.22 | 29.21,98.39 6.98,98.39 6.34,97.75 6.34,89.5 | X1.A32 1.9,89.5 1.27,88.86 1.27,41.24 2.54,39.97 2.54,8.22 5.08,8.22 5.08,2.5
  Bottom 0.61: 8.25,1.87 C1.- | 26.03,1.87 C2.-
  Bottom 0.813: X1.A32 6.34,89.5 X1.B32 | U4.1 30.48,34.89 32.38,36.79 33.02,37.43 v46.98,37.43 55.24,37.43 57.78,37.43 60.32,34.89 SV1.19 | U6.10 U5.11 50.16,31.71 54.6,31.71 | U5.10 55.88,31.08 55.24,31.71 54.6,31.71 | 54.6,31.71 C5.2 | 5.08,1.87 8.25,1.87 26.03,1.87 40.63,1.87 | 40.63,1.87 C6.2 | 40.63,1.87 52.7,1.87 53.34,2.5 53.34,6.31 53.97,6.95 U5.1 64.13,6.95 64.77,7.58 SV1.40 | SV2.3 SV2.1 | SV2.9 11.42,46.32 SV2.7 | SV1.22 66.04,32.35 66.67,32.98 66.67,57.75 | 66.67,57.75 SV1.2 | v57.78,53.94 57.78,55.84 61.59,59.65 66.04,59.65 66.67,59.02 66.67,57.75
  other vias: 19.05,95.85 72.39,3.14
  pour Top (isolate 0.305): -1.27,-0.67 77.47,-0.67 77.47,100.93 -1.27,100.93
  pour Bottom (isolate 0.305): -1.27,-0.67 77.47,-0.67 77.47,100.93 -1.27,100.93
IA0
  Bottom 0.305: U5.17 52.06,14.57 53.34,13.3 58.41,13.3 59.68,14.57 SV1.35
IA1
  Bottom 0.305: U5.15 52.06,19.65 53.34,18.38 58.41,18.38 59.68,17.11 SV1.33
IA2
  Top 0.305: SV1.36 63.49,13.3 60.95,13.3 60.32,12.66 60.32,10.12 58.41,8.22 50.79,8.22 50.16,8.85 50.16,16.47 49.52,17.11 U5.16
ICS0
  Bottom 0.305: SV1.37 61.59,12.03 57.78,8.22 53.97,8.22 52.7,9.49 U5.19
ICS1
  Bottom 0.305: SV1.38 63.49,13.3 60.95,13.3 58.41,10.76 53.34,10.76 52.06,12.03 U5.18
IIOR  (via drill 0.61)
  Top 0.305: v60.32,20.92 60.32,26.63 60.95,27.27 SV1.25
  Bottom 0.305: v60.32,20.92 53.34,20.92 52.06,22.19 U5.14
IIOW
  Bottom 0.305: U5.13 52.06,24.73 53.34,26 57.78,26 61.59,29.81 SV1.23
IRESET  (via drill 0.61)
  Top 0.305: v59.68,29.81 60.32,30.44 60.32,35.52 60.95,36.16 66.04,36.16 66.67,36.79 66.67,55.84 66.04,56.48 63.49,56.48 SV1.1
  Bottom 0.305: v59.68,29.81 58.41,28.54 53.34,28.54 52.06,27.27 U5.12
N$1
  Bottom 0.305: D1.A U6.19
N$2
  Top 0.305: U6.18 26.67,12.03 25.39,13.3 25.39,27.27 23.49,29.17 23.49,36.79 22.86,37.43 U4.19 18.41,37.43 17.78,38.06 D2.C
N$3  (via drill 0.61)
  Top 0.305: 16.51,79.34 16.51,83.78 15.87,84.42 U1.20 | 16.51,79.34 U1.22 | v27.3,14.57 27.3,22.19 26.67,22.82 26.67,27.27 24.12,29.81 24.12,37.74 23.49,38.38 23.49,45.05 24.12,45.68 24.12,60.29 21.59,62.83 21.59,74.26 20.32,75.53 17.14,75.53 16.51,76.16 16.51,79.34
  Bottom 0.305: v27.3,14.57 U6.17
N$4  (via drill 0.6)
  Top 0.305: v38.09,26 38.09,19.65 35.55,17.11 U6.16
  Bottom 0.305: U5.9 53.34,27.27 52.06,26 v38.09,26
N$5
  Top 0.305: U6.15 35.55,19.65 36.19,20.28 36.19,26.63 37.46,27.9 37.46,32.98 35.87,34.57 35.87,37.74 37.46,39.33 41.27,39.33 41.9,39.97 41.9,42.51 42.54,43.14 U3.21
N$6  (via drill 0.61)
  Top 0.305: v52.7,30.44 52.7,38.7 53.34,39.33 U3.1 55.24,39.33
  Bottom 0.305: v52.7,30.44 50.79,28.54 38.09,28.54 36.82,27.27 36.82,23.46 35.55,22.19 U6.14
N$7  (via drill 0.61)
  Top 0.305: v33.02,45.68 33.02,31.71 32.38,31.08 32.38,25.36 33.02,24.73 U6.13
  Bottom 0.305: v33.02,45.68 33.02,48.86 33.65,49.49 U2.21
N$8  (via drill 0.61)
  Top 0.305: v33.97,52.03 33.97,47.59 34.92,46.63 34.92,34.25 36.19,32.98 36.19,27.9 35.55,27.27 U6.12
  Bottom 0.305: v33.97,52.03 U2.23
N$9
  Top 0.305: 19.36,55.21 19.36,50.76 20,50.13 U4.14 | 19.36,55.21 U4.12 | RN1.3 19.36,55.21
  Bottom 0.305: SV2.2 RN1.3
N$10
  Bottom 0.305: U4.9 27.3,55.21 26.03,53.94 20.32,53.94 19.05,52.67 RN1.4 SV2.4
N$11
  Bottom 0.305: U4.7 27.3,50.13 26.03,51.4 20.32,51.4 19.05,50.13 RN1.5 SV2.6
N$12
  Bottom 0.305: U4.5 27.94,45.05 26.67,46.32 20.32,46.32 19.05,47.59 RN1.6 SV2.8
N$13
  Bottom 0.305: U4.3 27.3,39.97 23.49,43.78 19.68,43.78 18.41,45.05 RN1.7 SV2.10
N$14
  Top 0.305: R1.1 LED1.A
N$15
  Top 0.305: LED1.K 60.95,8.85 61.59,9.49 SV1.39
OE-RAM
  Bottom 0.305: U7.24 42.54,79.34 43.81,80.61 58.41,80.61 59.68,81.88 U8.17
R/W  (via drill 0.6, 0.61)
  Top 0.305: v24.76,67.91 v24.76,76.8 | v53.34,67.91 52.7,67.27 v52.7,53.3 53.34,52.67 53.34,42.51 53.97,41.87 U3.3 56.51,41.87 58.41,39.97 58.41,20.28 57.78,19.65 U5.6
  Bottom 0.305: U8.4 71.75,81.88 72.39,81.24 72.39,68.54 71.75,67.91 v53.34,67.91 44.45,67.91 43.17,66.64 U7.29 33.65,66.64 32.38,67.91 v24.76,67.91 | v24.76,76.8 17.78,76.8 16.51,75.53 10.79,75.53 9.52,74.26 X1.B26 | U6.8 40,24.73 39.36,24.09 39.36,21.55 40,20.92 52.06,20.92 53.34,19.65 U5.6 | v52.7,53.3 52.7,51.4 53.34,50.76 U2.3
RESET
  Bottom 0.305: U5.8 57.78,24.73 61.59,28.54 69.84,28.54 71.12,29.81 71.12,62.19 70.48,62.83 60.95,62.83 58.41,60.29 44.45,60.29 41.9,62.83 10.79,62.83 8.25,65.37 6.98,65.37 6.34,64.73 6.34,62.83 X1.B21
VCC  (via drill 0.61)
  Top 0.305: U3.24 45.08,39.65 45.08,40.28 U3.23
  Top 0.61: U1.28 U1.27 | v17.78,64.1 RN1.1 | U8.20 C4.1 62.22,60.29 56.51,54.57 v55.88,54.57 | v40.63,53.3 U7.32 | v31.75,59.02 29.21,61.56 U1.1 | 45.08,33.62 45.08,39.33 U3.24 | 45.08,33.62 45.08,7.58 45.71,6.95 U5.20 | 45.08,33.62 C5.1 v49.52,50.76 | C3.1 U4.20 | C3.1 15.87,31.08 14.6,29.81 14.6,26 | C3.1 21.59,29.81 24.12,27.27 24.12,7.58 24.76,6.95 26.03,6.95 | 26.03,6.95 U6.20 | 14.6,26 J7.P$1 | 14.6,26 IC5.3 | 26.03,6.95 C2.+
  Bottom 0.305: U2.22 46.35,50.76 46.98,51.4 46.98,53.3
  Bottom 0.406: SV1.20 63.49,33.62 57.14,33.62 55.88,34.89 50.79,34.89 C5.1
  Bottom 0.61: U1.1 v17.78,64.1 U1.28 | 49.52,53.3 46.98,53.3 U2.24 v40.63,53.3 | U2.1 55.88,53.3 v55.88,54.57 50.79,54.57 49.52,53.3 | U7.32 v31.75,59.02 | v49.52,50.76 49.52,53.3 | U6.20 35.55,5.68 | 35.55,5.68 C6.1 | 48.25,5.68 U5.20 | 35.55,5.68 48.25,5.68 | 48.25,5.68 R1.2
